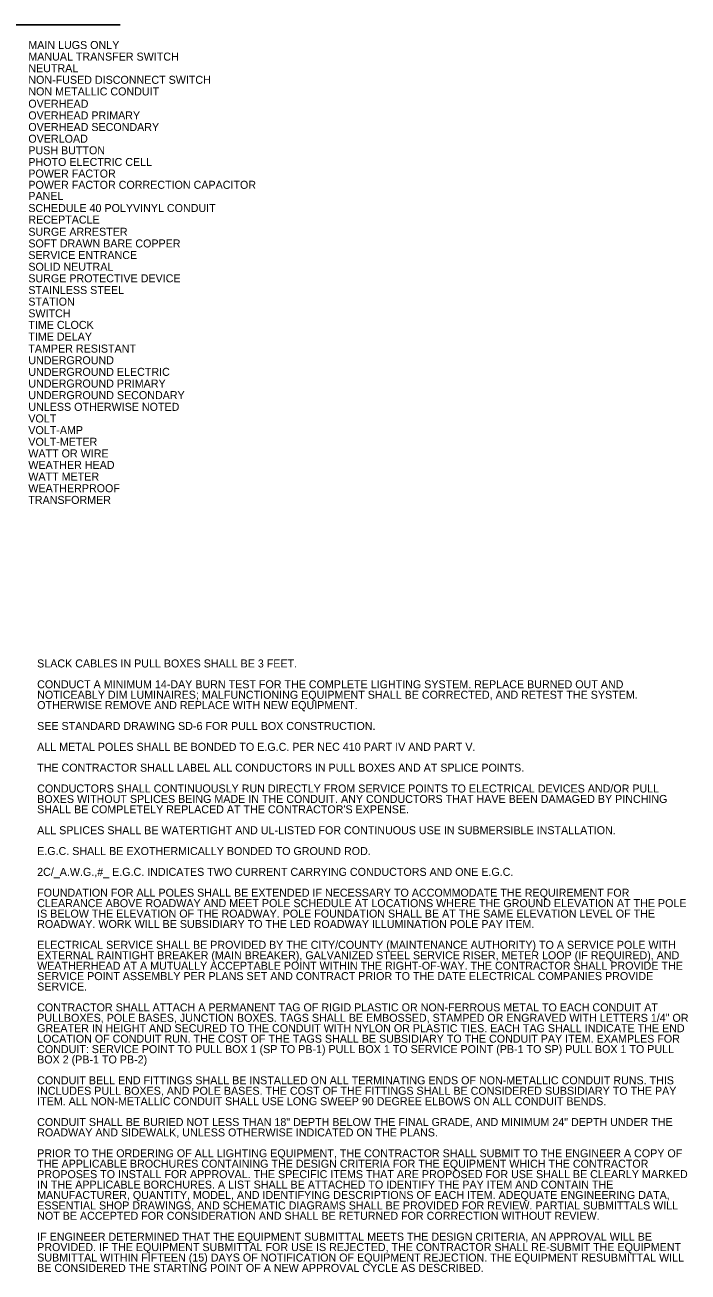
# Model space of a CAD drawing. Extents: x -3.65 to 4.44, y 0.05 to 1.76.
# Drawn here: x -2.448 to -1.585, y 0.121 to 1.743 of the extents above; entities that cross this region are included whole.
import ezdxf

# ---------------------------------------------------------------- set-up
doc = ezdxf.new("R2010")
doc.units = 0
doc.layers.add('E-ANNO-NOTE', color=7, linetype='Continuous')

msp = doc.modelspace()

# ---------------------------------------------------------------- linework, layer by layer
at = {"layer": 'E-ANNO-NOTE'}
msp.add_line((-2.7856, 1.7433), (-2.3242, 1.7433), dxfattribs=at)

# ---------------------------------------------------------------- texts
for s, height, p in [('MAIN LUGS ONLY', 0.010417, (-2.4437, 1.712)), ('MANUAL TRANSFER SWITCH', 0.010417, (-2.4437, 1.6969)), ('NEUTRAL', 0.01042, (-2.4437, 1.6818)), ('NON-FUSED DISCONNECT SWITCH', 0.010417, (-2.4437, 1.6667)), ('NON METALLIC CONDUIT', 0.010417, (-2.4437, 1.6516)), ('OVERHEAD', 0.01042, (-2.4437, 1.6356)), ('OVERHEAD PRIMARY', 0.010417, (-2.4437, 1.6204)), ('OVERHEAD SECONDARY', 0.010417, (-2.4437, 1.6053)), ('OVERLOAD', 0.01042, (-2.4437, 1.5901)), ('PUSH BUTTON', 0.010417, (-2.4437, 1.575)), ('PHOTO ELECTRIC CELL', 0.010417, (-2.4437, 1.5598)), ('POWER FACTOR', 0.010417, (-2.4437, 1.5447)), ('POWER FACTOR CORRECTION CAPACITOR', 0.010417, (-2.4437, 1.5301)), ('PANEL', 0.01042, (-2.4437, 1.5156)), ('SCHEDULE 40 POLYVINYL CONDUIT', 0.010417, (-2.4437, 1.4999)), ('RECEPTACLE', 0.01042, (-2.4437, 1.4848)), ('SURGE ARRESTER', 0.010417, (-2.4437, 1.469)), ('SOFT DRAWN BARE COPPER', 0.010417, (-2.4437, 1.4538)), ('SERVICE ENTRANCE', 0.010417, (-2.4437, 1.4387)), ('SOLID NEUTRAL', 0.010417, (-2.4437, 1.4235)), ('SURGE PROTECTIVE DEVICE', 0.010417, (-2.4437, 1.4084)), ('STAINLESS STEEL', 0.010417, (-2.4437, 1.3932)), ('STATION', 0.01042, (-2.4437, 1.3781)), ('SWITCH', 0.01042, (-2.4437, 1.3629)), ('TIME CLOCK', 0.01042, (-2.4437, 1.3478)), ('TIME DELAY', 0.01042, (-2.4437, 1.3326)), ('TAMPER RESISTANT', 0.010417, (-2.4437, 1.317)), ('UNDERGROUND', 0.010417, (-2.4437, 1.3018)), ('UNDERGROUND ELECTRIC', 0.010417, (-2.4437, 1.2867)), ('UNDERGROUND PRIMARY', 0.010417, (-2.4437, 1.2715)), ('UNDERGROUND SECONDARY', 0.010417, (-2.4437, 1.2564)), ('UNLESS OTHERWISE NOTED', 0.010417, (-2.4437, 1.2412)), ('VOLT', 0.01042, (-2.4437, 1.2261)), ('VOLT-AMP', 0.01042, (-2.4437, 1.2109)), ('VOLT-METER', 0.01042, (-2.4437, 1.1958)), ('WATT OR WIRE', 0.010417, (-2.4437, 1.1806)), ('WEATHER HEAD', 0.010417, (-2.4437, 1.1656)), ('WATT METER', 0.01042, (-2.4437, 1.1504)), ('WEATHERPROOF', 0.010417, (-2.4437, 1.1353)), ('TRANSFORMER', 0.010417, (-2.4437, 1.1201)), ('SLACK CABLES IN PULL BOXES SHALL BE 3 FEET.', 0.010417, (-2.4322, 0.9073)), ('CONDUCT A MINIMUM 14-DAY BURN TEST FOR THE COMPLETE LIGHTING SYSTEM. REPLACE BURNED OUT AND ', 0.010417, (-2.4322, 0.8802)), ('NOTICEABLY DIM LUMINAIRES; MALFUNCTIONING EQUIPMENT SHALL BE CORRECTED, AND RETEST THE SYSTEM. ', 0.010417, (-2.4322, 0.8666)), ('OTHERWISE REMOVE AND REPLACE WITH NEW EQUIPMENT.', 0.010417, (-2.4322, 0.8531)), ('SEE STANDARD DRAWING SD-6 FOR PULL BOX CONSTRUCTION.', 0.010417, (-2.4322, 0.8259)), ('ALL METAL POLES SHALL BE BONDED TO E.G.C. PER NEC 410 PART IV AND PART V.', 0.010417, (-2.4322, 0.7988)), ('THE CONTRACTOR SHALL LABEL ALL CONDUCTORS IN PULL BOXES AND AT SPLICE POINTS.', 0.010417, (-2.4322, 0.7717)), ('CONDUCTORS SHALL CONTINUOUSLY RUN DIRECTLY FROM SERVICE POINTS TO ELECTRICAL DEVICES AND/OR PULL ', 0.010417, (-2.4322, 0.7446)), ('BOXES WITHOUT SPLICES BEING MADE IN THE CONDUIT. ANY CONDUCTORS THAT HAVE BEEN DAMAGED BY PINCHING ', 0.010417, (-2.4322, 0.731)), ("SHALL BE COMPLETELY REPLACED AT THE CONTRACTOR'S EXPENSE.", 0.010417, (-2.4322, 0.7175)), ('ALL SPLICES SHALL BE WATERTIGHT AND UL-LISTED FOR CONTINUOUS USE IN SUBMERSIBLE INSTALLATION.', 0.010417, (-2.4322, 0.6903)), ('E.G.C. SHALL BE EXOTHERMICALLY BONDED TO GROUND ROD.', 0.010417, (-2.4322, 0.6632)), ('2C/_A.W.G.,#_ E.G.C. INDICATES TWO CURRENT CARRYING CONDUCTORS AND ONE E.G.C.', 0.010417, (-2.4322, 0.6361)), ('FOUNDATION FOR ALL POLES SHALL BE EXTENDED IF NECESSARY TO ACCOMMODATE THE REQUIREMENT FOR ', 0.010417, (-2.4322, 0.609)), ('CLEARANCE ABOVE ROADWAY AND MEET POLE SCHEDULE AT LOCATIONS WHERE THE GROUND ELEVATION AT THE POLE ', 0.010417, (-2.4322, 0.5954)), ('IS BELOW THE ELEVATION OF THE ROADWAY. POLE FOUNDATION SHALL BE AT THE SAME ELEVATION LEVEL OF THE ', 0.010417, (-2.4322, 0.5818)), ('ROADWAY. WORK WILL BE SUBSIDIARY TO THE LED ROADWAY ILLUMINATION POLE PAY ITEM.', 0.010417, (-2.4322, 0.5683)), ('ELECTRICAL SERVICE SHALL BE PROVIDED BY THE CITY/COUNTY (MAINTENANCE AUTHORITY) TO A SERVICE POLE WITH ', 0.0104166, (-2.4322, 0.5412)), ('EXTERNAL RAINTIGHT BREAKER (MAIN BREAKER), GALVANIZED STEEL SERVICE RISER, METER LOOP (IF REQUIRED), AND ', 0.0104166, (-2.4322, 0.5276)), ('WEATHERHEAD AT A MUTUALLY ACCEPTABLE POINT WITHIN THE RIGHT-OF-WAY. THE CONTRACTOR SHALL PROVIDE THE ', 0.0104166, (-2.4322, 0.514)), ('SERVICE POINT ASSEMBLY PER PLANS SET AND CONTRACT PRIOR TO THE DATE ELECTRICAL COMPANIES PROVIDE ', 0.010417, (-2.4322, 0.5005)), ('SERVICE.', 0.01042, (-2.4322, 0.4869)), ('CONTRACTOR SHALL ATTACH A PERMANENT TAG OF RIGID PLASTIC OR NON-FERROUS METAL TO EACH CONDUIT AT ', 0.010417, (-2.4322, 0.4598)), ('PULLBOXES, POLE BASES, JUNCTION BOXES. TAGS SHALL BE EMBOSSED, STAMPED OR ENGRAVED WITH LETTERS 1/4" OR ', 0.0104166, (-2.4322, 0.4462)), ('GREATER IN HEIGHT AND SECURED TO THE CONDUIT WITH NYLON OR PLASTIC TIES. EACH TAG SHALL INDICATE THE END ', 0.0104166, (-2.4322, 0.4327)), ('LOCATION OF CONDUIT RUN. THE COST OF THE TAGS SHALL BE SUBSIDIARY TO THE CONDUIT PAY ITEM. EXAMPLES FOR ', 0.0104166, (-2.4322, 0.4191)), ('CONDUIT: SERVICE POINT TO PULL BOX 1 (SP TO PB-1) PULL BOX 1 TO SERVICE POINT (PB-1 TO SP) PULL BOX 1 TO PULL ', 0.0104166, (-2.4322, 0.4055)), ('BOX 2 (PB-1 TO PB-2)', 0.010417, (-2.4322, 0.392)), ('CONDUIT BELL END FITTINGS SHALL BE INSTALLED ON ALL TERMINATING ENDS OF NON-METALLIC CONDUIT RUNS. THIS ', 0.0104166, (-2.4322, 0.3649)), ('INCLUDES PULL BOXES, AND POLE BASES. THE COST OF THE FITTINGS SHALL BE CONSIDERED SUBSIDIARY TO THE PAY ', 0.0104166, (-2.4322, 0.3513)), ('ITEM. ALL NON-METALLIC CONDUIT SHALL USE LONG SWEEP 90 DEGREE ELBOWS ON ALL CONDUIT BENDS.', 0.010417, (-2.4322, 0.3377)), ('CONDUIT SHALL BE BURIED NOT LESS THAN 18" DEPTH BELOW THE FINAL GRADE, AND MINIMUM 24" DEPTH UNDER THE ', 0.0104166, (-2.4322, 0.3106)), ('ROADWAY AND SIDEWALK, UNLESS OTHERWISE INDICATED ON THE PLANS.', 0.010417, (-2.4322, 0.2971)), ('PRIOR TO THE ORDERING OF ALL LIGHTING EQUIPMENT, THE CONTRACTOR SHALL SUBMIT TO THE ENGINEER A COPY OF ', 0.0104166, (-2.4322, 0.2699)), ('THE APPLICABLE BROCHURES CONTAINING THE DESIGN CRITERIA FOR THE EQUIPMENT WHICH THE CONTRACTOR ', 0.010417, (-2.4322, 0.2564)), ('PROPOSES TO INSTALL FOR APPROVAL. THE SPECIFIC ITEMS THAT ARE PROPOSED FOR USE SHALL BE CLEARLY MARKED ', 0.0104166, (-2.4322, 0.2428)), ('IN THE APPLICABLE BORCHURES. A LIST SHALL BE ATTACHED TO IDENTIFY THE PAY ITEM AND CONTAIN THE ', 0.010417, (-2.4322, 0.2292)), ('MANUFACTURER, QUANTITY, MODEL, AND IDENTIFYING DESCRIPTIONS OF EACH ITEM. ADEQUATE ENGINEERING DATA, ', 0.0104166, (-2.4322, 0.2157)), ('ESSENTIAL SHOP DRAWINGS, AND SCHEMATIC DIAGRAMS SHALL BE PROVIDED FOR REVIEW. PARTIAL SUBMITTALS WILL ', 0.0104166, (-2.4322, 0.2021)), ('NOT BE ACCEPTED FOR CONSIDERATION AND SHALL BE RETURNED FOR CORRECTION WITHOUT REVIEW.', 0.010417, (-2.4322, 0.1886)), ('IF ENGINEER DETERMINED THAT THE EQUIPMENT SUBMITTAL MEETS THE DESIGN CRITERIA, AN APPROVAL WILL BE ', 0.010417, (-2.4322, 0.1614)), ('PROVIDED. IF THE EQUIPMENT SUBMITTAL FOR USE IS REJECTED, THE CONTRACTOR SHALL RE-SUBMIT THE EQUIPMENT ', 0.0104166, (-2.4322, 0.1479)), ('SUBMITTAL WITHIN FIFTEEN (15) DAYS OF NOTIFICATION OF EQUIPMENT REJECTION. THE EQUIPMENT RESUBMITTAL WILL ', 0.0104166, (-2.4322, 0.1343)), ('BE CONSIDERED THE STARTING POINT OF A NEW APPROVAL CYCLE AS DESCRIBED.', 0.010417, (-2.4322, 0.1208))]:
    msp.add_text(s, height=height, dxfattribs=at).set_placement(p)

doc.saveas('drawing.dxf')
